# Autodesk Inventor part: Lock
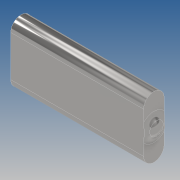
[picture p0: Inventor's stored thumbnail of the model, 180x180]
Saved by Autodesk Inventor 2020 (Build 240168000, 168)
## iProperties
Created: 2019-10
Part Number: Lock
Material: Generic
Document SubType Name: Modeling
Designer: yello
Density: 1 g/cm^3
Appearance: Default
Author: yello
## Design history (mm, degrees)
sketch "Sketch1"
  geometry: L1 (0, 0)-(4, 0); L2 (0, -1)-(4, -1); L3 (4, 1)-(0, 1); A1 r 1 centre (0, 0) between (0, 1) and (0, -1); A2 r 1 centre (4, 0) between (4, -1) and (4, 1); 1 further point
  constraints: 8 end point, 4 point on circle, 4 tangent, 2 centre point, 1 horizontal, 1 midpoint, 1 parallel
  dimensions: "d0" = 4 distance of L1.start L1.end; "d1" = 2 diameter of A2
extrude "Extrusion1" new body sketch "Sketch1" distance "d2" = 13; taper "d3" = 0 deg
workplane "Work Plane1"
sketch "Sketch3"
  geometry: L1 (0, 4)-(0, 0); C1 r 1 at (0, 2); C2 r 1 at (0, 2); A1 r 1 centre (0, 4) between (1, 4) and (-1, 4); A2 r 1 centre (0, 0) between (-1, 0) and (1, 0); 3 further points
  constraints: 4 centre point, 4 point on circle, 2 end point, 1 coincident
  dimensions: "d6" = 2 diameter of C2
revolve "Revolution1" sketch "Sketch3" stored, may be unused: angle "d7" = 90 deg
fillet "Fillet1" dims "d8" = 1
body "Solid1"
other parameters: "d5" = -0.5
